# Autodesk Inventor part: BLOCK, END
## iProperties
Author: Elise Moss
Created: 2001-08
Part Number: BLOCK, END
Document SubType Name: Modeling
Designer: Elise Moss
Control State: 0
Master: False
Checked Out: False
PropertySet Name: Design Tracking Control
Shininess: 20.0
PropertySet Name: _Private Model Information
Length Units: 11269
Angle Units: 11283
Time Units: 11279
Mass Units: 11290
Length Display Precision: 3
Angle Display Precision: 2
Compacted: False
Density: 0.0
Volumn: 0.0
Area: 0.0
PropertySet Name: Model Information
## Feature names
1. Extrusion1
